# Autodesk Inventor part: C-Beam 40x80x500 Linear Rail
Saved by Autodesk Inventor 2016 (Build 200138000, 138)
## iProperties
Created: 2016-01
Part Number: C-Beam 40x80x500 Linear Rail
Material: Generic
Document SubType Name: Modeling
Designer: John
Density: 1 g/cm^3
Appearance: Default
Author: John
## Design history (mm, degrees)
feature "BOSS-EXTRUDE1"
body "Solid1"
